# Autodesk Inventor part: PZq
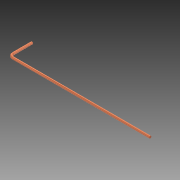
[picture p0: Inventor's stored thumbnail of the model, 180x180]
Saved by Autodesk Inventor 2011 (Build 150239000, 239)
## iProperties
Created: 2015-02
Part Number: PZq
Document SubType Name: Modeling
Designer: Evgeny
Density: 1 g/cm^3
Mass: 0.0974238 g
Surface Area: 3.27008 cm^2
Volume: 0.0974238 cm^3
Author: Evgeny
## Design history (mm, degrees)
sketch "Эскиз1"
  geometry: L1 (0, 0)-(0, -10); L2 (2, -12)-(75, -12); A1 r 2 centre (2, -10) between (0, -10) and (2, -12)
  constraints: 4 end point, 2 point on circle, 2 tangent, 1 centre point, 1 perpendicular, 1 vertical
  dimensions: "d0" = 2 radius of A1; "d1" = 75 distance from line of L2.end L1; "d2" = 12 distance from line of L1.start L2
sketch "Эскиз2"
  geometry: C1 r 0.6 at (0, 0); 1 further point
  constraints: 1 centre point, 1 coincident
  dimensions: "d3" = 1.2 diameter of C1
feature "Сдвиг1" sketch "Эскиз1", "Эскиз2" dims "d4" = 0
node "Твердое тело1"
